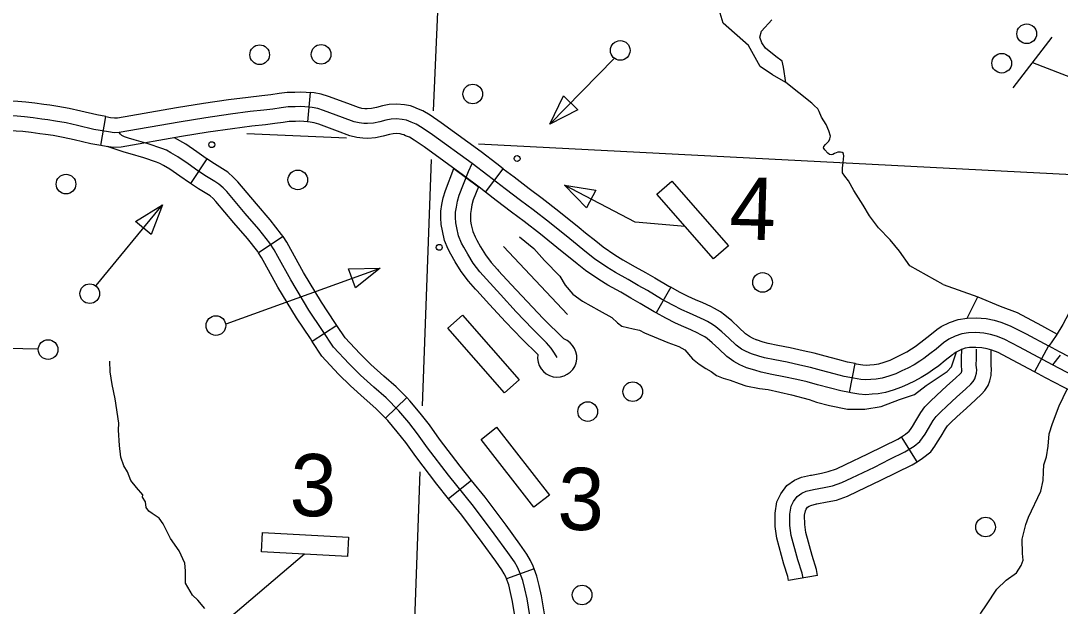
# Model space of a CAD drawing. Extents: x 653372 to 905732, y 627442 to 787275.
# Drawn here: x 714058 to 719343, y 754665 to 757645 of the extents above; entities that cross this region are included whole.
import ezdxf

# ---------------------------------------------------------------- set-up
doc = ezdxf.new("R2010")
doc.units = 0
for name, color, linetype in [('31', 7, 'Continuous'), ('32', 7, 'Continuous'), ('35', 7, 'Continuous'), ('45', 7, 'Continuous'), ('5', 7, 'Continuous'), ('56', 7, 'Continuous')]:
    doc.layers.add(name, color=color, linetype=linetype)

msp = doc.modelspace()

# ---------------------------------------------------------------- linework, layer by layer
at = {"layer": '31'}
for p, q in [((715529.1, 757279.6), (715516.5, 757130.2)), ((714464.6, 757009.8), (714490.5, 757157.5)), ((714490.5, 757157.5), (714490.5, 757157.5)), ((716420, 756772.8), (716511.3, 756891.8)), ((716511.3, 756891.8), (716511.3, 756891.8)), ((717362.4, 756288.6), (717288.8, 756157.9)), ((719283, 755990.6), (719212.1, 755858.4)), ((718271.2, 755753.4), (718299.6, 755900.6)), ((718299.6, 755900.6), (718299.6, 755900.6))]:
    msp.add_line(p, q, dxfattribs=at)
for points in [[(714986.5, 757225.6), (714987.8, 757225.9), (715114.1, 757244.3), (715214.9, 757257), (715284.1, 757264.4), (715329.3, 757270.3), (715372.1, 757276.5), (715411.7, 757281.5), (715451.2, 757282.5), (715479.3, 757283.4), (715508.5, 757281.4), (715529.1, 757279.6)], [(716061.3, 757202.9), (716040.2, 757211.4), (716008.6, 757217.5), (715970.2, 757221.3), (715931.2, 757219), (715896.3, 757211.7), (715866.5, 757203.3), (715840.7, 757198.6), (715818.6, 757196.7), (715808.1, 757197), (715792.2, 757198.8), (715774.6, 757203), (715720.9, 757223.5), (715621.9, 757260.3), (715585.1, 757271.7), (715549.2, 757277.9), (715529.1, 757279.6)], [(714490.5, 757157.5), (714444.3, 757165.6), (714362.8, 757185.2), (714303.2, 757198.7), (714246.7, 757208.7), (714205.4, 757215.3), (714174.6, 757219.2), (714129.8, 757225), (714083.2, 757230.6), (714042.7, 757233.7), (713980.6, 757235.5), (713956.8, 757235.6)], [(714490.5, 757157.5), (714514.5, 757153.3), (714535.1, 757150.7), (714550.1, 757151.6), (714850.2, 757203.3), (714986.5, 757225.6)], [(719135.7, 755984.5), (719058.1, 756024.5), (719018.4, 756039.8), (718989, 756047.7), (718955.5, 756055.1), (718914.7, 756057.7), (718875.9, 756056), (718842, 756051.4), (718808.5, 756039.7), (718776.4, 756023.8), (718749.8, 756005.6), (718711.5, 755974.3), (718680.5, 755949.2), (718649.5, 755926.9), (718628.7, 755912), (718599.7, 755894.7), (718567.5, 755877.3), (718537.5, 755862.7), (718507.5, 755848.8), (718471.2, 755835.8), (718437.1, 755826.3), (718407.4, 755820.9), (718380.5, 755818.8), (718355.1, 755816.8), (718328.5, 755819.7), (718292, 755825.7), (718244.4, 755834.9), (718193.4, 755848.4), (718128.8, 755865.1), (718073.6, 755880.2), (718019.7, 755891.7), (717954, 755907), (717891.7, 755918.7), (717839.9, 755930.2), (717811.3, 755938.1), (717773.6, 755949.8), (717745.8, 755961.2), (717722.9, 755973.8), (717695.5, 755993.6), (717657.8, 756029.3), (717622.9, 756062), (717592.7, 756087.6), (717575.4, 756099.4), (717548.9, 756114.8), (717532.9, 756123), (717496.1, 756140.3), (717458.6, 756156.2), (717419, 756173.6), (717372.5, 756196.8), (717315.7, 756228.8), (717244.5, 756271.8), (717196.7, 756297.9), (717145.5, 756328.3), (717081, 756363.4), (717037.5, 756390.7), (716974.7, 756433.8), (716934.1, 756466), (716849.6, 756534.8), (716746.4, 756617.5), (716663.2, 756682.7), (716598.5, 756731.1), (716520.3, 756790.4), (716433.4, 756857.1), (716353.7, 756917.9), (716151.5, 757064.7), (716098.6, 757100.8), (716067.7, 757119.2), (716043, 757129.4), (716018.9, 757139.1), (715997.6, 757143.3), (715968.8, 757146.1), (715941.2, 757144.5), (715914.1, 757138.8), (715883.4, 757130.2), (715850.7, 757124.2), (715820.7, 757121.6), (715802.7, 757122.1), (715779.3, 757124.8), (715752.5, 757131.1), (715694.4, 757153.4), (715597.7, 757189.2), (715567.5, 757198.6), (715539.6, 757203.5), (715502.8, 757206.6), (715477.9, 757208.3), (715453.4, 757207.6), (715417.4, 757206.7), (715382.3, 757202.2), (715339.6, 757196), (715293, 757189.9), (715223.5, 757182.5), (715124.2, 757170), (714999.3, 757151.8), (714862.6, 757129.4), (714558.8, 757077)], [(716511.3, 756891.8), (716479, 756916.7), (716398.5, 756978.1), (716194.7, 757126), (716139, 757164), (716101.4, 757186.4), (716071.4, 757198.8), (716061.3, 757202.9)], [(714558.8, 757077), (714532.7, 757075.4), (714503.3, 757079.1), (714429, 757092.1), (714345.7, 757112.2), (714288.4, 757125.2), (714234.3, 757134.8), (714194.9, 757141), (714165, 757144.8), (714120.5, 757150.6), (714076, 757155.9), (714038.7, 757158.7), (713979.3, 757160.5), (713829.8, 757161), (713646, 757164.3), (713525.8, 757173.6)], [(715516.5, 757130.2), (715497, 757131.8), (715476.4, 757133.3), (715455.5, 757132.6), (715423, 757131.8), (715392.4, 757127.9), (715349.9, 757121.7), (715301.8, 757115.4), (715232.2, 757108), (715134.3, 757095.7), (715010.8, 757077.6), (715010.7, 757077.6)], [(716005.3, 757063.7), (715997.5, 757066.9), (715986.7, 757069), (715967.3, 757070.9), (715951.2, 757069.9), (715931.9, 757065.9), (715900.3, 757057.1), (715860.8, 757049.8), (715822.8, 757046.5), (715797.3, 757047.3), (715766.4, 757050.8), (715730.4, 757059.3), (715668, 757083.2), (715573.5, 757118.2), (715549.8, 757125.6), (715530.1, 757129), (715516.5, 757130.2)], [(714464.6, 757009.8), (714413.8, 757018.6), (714328.6, 757039.1), (714273.5, 757051.7), (714221.9, 757060.8), (714184.4, 757066.8), (714155.5, 757070.4), (714111.2, 757076.2), (714068.7, 757081.3), (714034.8, 757083.8), (713978.1, 757085.5), (713956.2, 757085.6)], [(715010.7, 757077.6), (714875, 757055.4), (714567.5, 757002.4), (714530.2, 757000.1), (714492.2, 757005), (714464.6, 757009.8)], [(716420, 756772.8), (716387.9, 756797.5), (716308.9, 756857.8), (716108.3, 757003.3), (716058.3, 757037.5), (716034, 757052), (716014.7, 757060), (716005.3, 757063.7)], [(716376.4, 756271.7), (716369.5, 756279.2), (716334, 756320), (716297.1, 756368.2), (716266.4, 756418.1), (716243.9, 756456.4), (716231, 756482.5), (716212.5, 756527.1), (716201.5, 756575.7), (716195.4, 756607.7), (716193.7, 756641.7), (716193.9, 756676.3), (716199.2, 756709.2), (716205.1, 756743.4), (716216.6, 756781.8), (716259.5, 756893.6), (716384.4, 756800.2)], [(716785.1, 755931.3), (716771, 755952.9), (716754.8, 755978), (716731.7, 756006.2), (716660.6, 756077.3), (716577.6, 756164), (716496.4, 756251.7), (716425.5, 756329.2), (716392.1, 756367.5), (716358.9, 756410.8), (716330.7, 756456.7), (716310, 756492.1), (716299.3, 756513.6), (716284.2, 756549.9), (716274.9, 756591.1), (716270.1, 756616.6), (716268.7, 756643.4), (716268.8, 756670.1), (716273.2, 756696.8), (716278.3, 756726.2), (716287.7, 756757.6), (716309.1, 756813.3), (716334.9, 756877.4), (716353.7, 756917.9)], [(716511.3, 756891.8), (716565.8, 756850.1), (716643.6, 756791), (716708.8, 756742.2), (716793, 756676.3), (716896.7, 756593.1), (716929.7, 756566.3)], [(716384.4, 756800.2), (716358.7, 756733.4), (716351.4, 756709), (716347.1, 756684.4), (716343.8, 756664), (716343.8, 756645.1), (716344.7, 756625.5), (716348.3, 756606.4), (716356, 756572.8), (716367.7, 756544.6), (716376, 756527.8), (716395.1, 756495.3), (716420.8, 756453.3), (716450.2, 756415), (716481.5, 756379.1), (716487.1, 756373)], [(716835.1, 756449.9), (716802.5, 756476.4), (716699.9, 756558.7), (716617.6, 756623.1), (716553.3, 756671.2), (716474.8, 756730.8), (716420, 756772.8)], [(716929.7, 756566.3), (716981.1, 756524.5), (717019.3, 756494.2), (717078.7, 756453.4), (717118.9, 756428.1), (717182.5, 756393.5), (717233.8, 756363.1), (717281.8, 756336.9), (717353.5, 756293.6), (717362.4, 756288.6)], [(717288.8, 756157.9), (717277.9, 756164), (717207.1, 756206.8), (717159.5, 756232.7), (717108.4, 756263.1), (717043.1, 756298.6), (716996.3, 756328), (716930.1, 756373.5), (716887.2, 756407.6), (716835.1, 756449.9)], [(716487.1, 756373), (716551.6, 756302.5), (716632.1, 756215.4), (716714.3, 756129.8), (716818.3, 756025.6)], [(716686.2, 755945.7), (716607, 756024.9), (716523, 756112.6), (716441.2, 756200.9), (716376.4, 756271.7)], [(717800.8, 756019.7), (717778.3, 756028.9), (717763.2, 756037.3), (717743.4, 756051.5), (717709.3, 756083.9), (717672.8, 756118.1), (717638.2, 756147.3), (717615.4, 756162.9), (717584.9, 756180.6), (717566.1, 756190.3), (717526.7, 756208.8), (717488.3, 756225.1), (717450.8, 756241.5), (717407.7, 756263.1), (717362.4, 756288.6)], [(717743.9, 755880.9), (717713.3, 755893.4), (717682.7, 755910.4), (717647.6, 755935.7), (717606.4, 755974.7), (717573, 756006), (717547.2, 756027.8), (717535.5, 756035.9), (717512.9, 756048.9), (717499.8, 756055.7), (717465.5, 756071.8), (717428.9, 756087.3), (717387.1, 756105.7), (717337.3, 756130.6), (717288.8, 756157.9)], [(718716.5, 756073.7), (718738.3, 756088.7), (718779.4, 756109), (718824.4, 756124.7), (718869.3, 756130.8), (718915.5, 756132.8), (718965.9, 756129.5), (719006.8, 756120.6), (719041.7, 756111.2), (719088.8, 756093), (719170.6, 756050.9), (719283, 755990.6)], [(718299.6, 755900.6), (718305.2, 755899.6), (718338.6, 755894), (718356.2, 755892.1), (718374.7, 755893.6), (718397.8, 755895.3), (718420.2, 755899.4), (718448.4, 755907.3), (718479, 755918.3), (718505.3, 755930.5), (718533.3, 755944.1), (718562.6, 755959.9), (718587.6, 755974.8), (718605.8, 755987.8), (718634.9, 756008.8), (718664.2, 756032.5), (718704.8, 756065.7), (718716.5, 756073.7)], [(718299.6, 755900.6), (718261.1, 755908.1), (718212.4, 755921), (718148, 755937.6), (718091.3, 755953.1), (718036.1, 755964.9), (717969.5, 755980.4), (717906.7, 755992.2), (717858, 756003), (717832.4, 756010), (717799, 756020.4), (717800.8, 756019.7)], [(719212.1, 755858.4), (719100.8, 755918.1), (719027.3, 755956), (718995.1, 755968.4), (718971.2, 755974.8), (718945, 755980.6), (718913.9, 755982.6), (718882.6, 755981.3), (718859.6, 755978.1), (718837.7, 755970.5), (718814.4, 755958.9), (718801.3, 755949.9)], [(719442.4, 755821.2), (719303.9, 755894.3), (719135.7, 755984.5)], [(719702.6, 755600.9), (719700.3, 755623.4), (719690.5, 755664.1), (719675, 755704.8), (719651.2, 755742.5), (719630.3, 755770.3), (719602.2, 755799.4), (719576.4, 755824), (719538.4, 755850.5), (719479.5, 755886.4), (719339.1, 755960.5), (719283, 755990.6)], [(718801.2, 755949.9), (718794.8, 755945.5), (718758.8, 755916.1), (718726, 755889.6), (718693.2, 755865.9), (718669.8, 755849.2), (718636.8, 755829.4), (718601.7, 755810.6), (718569.6, 755795), (718535.9, 755779.4), (718494, 755764.3), (718454, 755753.1), (718416.9, 755746.4), (718386.4, 755744.1), (718354.1, 755741.5), (718318.3, 755745.4), (718278.8, 755751.9), (718271.2, 755753.4)], [(718271.2, 755753.4), (718227.7, 755761.7), (718174.4, 755775.9), (718109.5, 755792.7), (718055.9, 755807.3), (718003.4, 755818.5), (717938.5, 755833.6), (717876.7, 755845.3), (717821.9, 755857.3), (717790.2, 755866.1), (717748.2, 755879.1), (717743.9, 755880.9)], [(719553.4, 755585.3), (719552.1, 755598), (719546.9, 755619.8), (719540.2, 755637.5), (719527.7, 755657.2), (719516.1, 755672.7), (719496.4, 755692.9), (719481.1, 755707.6), (719456.4, 755724.8), (719405.3, 755756), (719268.7, 755828.1), (719212.1, 755858.4)]]:
    msp.add_lwpolyline(points, dxfattribs=at)
msp.add_arc((716785.1, 755931.3), 100, 171.739, 70.6256, dxfattribs=at)
at = {"layer": '32'}
for p, q in [((715003.8, 756941.7), (714921.6, 756816.2)), ((715391.5, 756546.6), (715266.4, 756463.8)), ((715665.2, 756094.8), (715539.5, 756013)), ((716020, 755727), (715913.1, 755621.8)), ((716350.1, 755305.5), (716233, 755211.8)), ((716668.2, 754856.1), (716527.5, 754804.1))]:
    msp.add_line(p, q, dxfattribs=at)
for points in [[(716652.6, 754575.1), (716632.2, 754703.5), (716621.5, 754753), (716610.6, 754795.7), (716594.4, 754839.5), (716583, 754864.2), (716568.2, 754890.4), (716535.1, 754938.2), (716464.9, 755033.7), (716359.2, 755174.2), (716232.5, 755332.3), (716126.7, 755471.8), (716075.4, 755543.4), (716030.3, 755600.3), (715980.6, 755660.2), (715915.4, 755726.4), (715853.7, 755779.9), (715785.5, 755841.3), (715727.9, 755899), (715647.7, 755984.2), (715592.8, 756068.6), (715522.9, 756172.9), (715430.2, 756326.6), (715364.7, 756445.4), (715345.8, 756479.8), (715323.4, 756513.6), (715268.6, 756584.4), (715199, 756664.8), (715105, 756775.7), (715087.6, 756794.2), (715065.3, 756813.9), (715043.8, 756827.2), (715002.2, 756853), (714957.8, 756882.1), (714909.2, 756916.2), (714856.3, 756953.3), (714820.9, 756973.4), (714798.4, 756985.7), (714775.8, 756995.7), (714705.2, 757019.2), (714634.7, 757039.3), (714606.3, 757047.5), (714585.1, 757054.4), (714571.2, 757061.7), (714564.1, 757068.7), (714558.8, 757077)], [(715003.8, 756941.7), (714999.9, 756944.2), (714952.3, 756977.6), (714896.4, 757016.8), (714839.1, 757049.2)], [(714921.6, 756816.2), (714915.7, 756820), (714866.1, 756854.8), (714816.2, 756889.8), (714784.4, 756907.9), (714765.2, 756918.4), (714748.8, 756925.6), (714683, 756947.5), (714614.1, 756967.2), (714584.2, 756975.8), (714497.5, 757004.3)], [(715391.5, 756546.6), (715384.4, 756557.3), (715326.7, 756631.9), (715256, 756713.6), (715161, 756825.7), (715139.8, 756848.2), (715110.1, 756874.3), (715083.3, 756890.9), (715042.6, 756916.3), (715003.8, 756941.7)], [(715266.4, 756463.8), (715262.4, 756469.9), (715210.6, 756536.8), (715142, 756616), (715049.1, 756725.7), (715035.3, 756740.3), (715020.4, 756753.5), (715004.3, 756763.5), (714961.9, 756789.8), (714921.6, 756816.2)], [(715665.2, 756094.8), (715655.4, 756109.9), (715586.2, 756213.2), (715495.2, 756364.1), (715430.4, 756481.6), (715410, 756518.6), (715391.5, 756546.6)], [(715539.5, 756013), (715530.2, 756027.3), (715459.6, 756132.6), (715365.3, 756289.1), (715299, 756409.2), (715281.5, 756441), (715266.4, 756463.8)], [(719563.3, 756393.3), (719511.2, 756333.2), (719478.2, 756295.1), (719452.7, 756258.8), (719426.6, 756224.2), (719400.6, 756182.9), (719356, 756100), (719322.8, 756043), (719284.6, 755989.7)], [(716020, 755727), (715966.8, 755781.1), (715903.4, 755836.1), (715837.2, 755895.7), (715781.7, 755951.2), (715706.9, 756030.7), (715665.2, 756094.8)], [(715913.1, 755621.8), (715864, 755671.7), (715804.1, 755723.6), (715733.8, 755786.9), (715674, 755846.8), (715588.5, 755937.7), (715539.5, 756013)], [(719343.6, 755943.3), (719303.9, 755894.3)], [(716350.1, 755305.5), (716291.7, 755378.4), (716187.1, 755516.3), (716135.3, 755588.6), (716088.6, 755647.5), (716036.2, 755710.5), (716020, 755727)], [(716233, 755211.8), (716173.4, 755286.2), (716066.4, 755427.3), (716015.5, 755498.3), (715972.1, 755553), (715924.9, 755609.8), (715913.1, 755621.8)], [(716668.2, 754856.1), (716663.7, 754868.3), (716649.8, 754898.4), (716631.8, 754930.3), (716596.1, 754981.7), (716525.1, 755078.5), (716418.4, 755220.2), (716350.1, 755305.5)], [(716527.5, 754804.1), (716525.1, 754810.7), (716516.2, 754830), (716504.6, 754850.6), (716474, 754894.6), (716404.7, 754989), (716299.9, 755128.2), (716233, 755211.8)], [(716768, 754322.8), (716764.7, 754345.1), (716740.4, 754489.8), (716726.8, 754586.3), (716705.9, 754717.3), (716694.5, 754770.2), (716682.3, 754818), (716668.2, 754856.1)], [(716619.7, 754300.7), (716616.6, 754321.6), (716592.2, 754466.9), (716578.5, 754564), (716558.4, 754689.7), (716548.5, 754735.8), (716538.9, 754773.3), (716527.5, 754804.1)]]:
    msp.add_lwpolyline(points, dxfattribs=at)
at = {"layer": '35'}
for points in [[(718079.8, 757226.2), (717947.3, 757330.7), (717879.3, 757370.3), (717816.8, 757413), (717757.3, 757518.5), (717628.9, 757632.3), (717614.8, 757683.6)], [(717947.3, 757330.7), (717936, 757409.3), (717929.1, 757438.9), (717896.5, 757463.3), (717845, 757506), (717826.2, 757532), (717815.4, 757561.7), (717824.1, 757592.7), (717876.7, 757649.9)], [(718747.9, 756303.1), (718578.9, 756397), (718525.9, 756472.4), (718479, 756530.9), (718418.8, 756591.4), (718373.6, 756651.5), (718341.7, 756706.1), (718293.7, 756781.4), (718266.6, 756829.7), (718247.2, 756853.8), (718236.8, 756871.7), (718235.9, 756895.2), (718239.2, 756923.6), (718243.6, 756956.9), (718240.5, 756965.5), (718240.6, 756969.7), (718234.9, 756974.9), (718225.7, 756976.9), (718213.1, 756975.6), (718195.3, 756969.4), (718187.6, 756963.8), (718179.2, 756963.2), (718169.2, 756965.2), (718161.8, 756970.4), (718146.4, 756987.7), (718140, 756997.9), (718141.9, 757005.4), (718148.9, 757015.3), (718166.2, 757031.5), (718172.4, 757043.9), (718174.5, 757058.1), (718166.9, 757085.2), (718153.6, 757116.6), (718128.8, 757155.1), (718117.9, 757183.1), (718109.9, 757196.8), (718091.2, 757214.1), (718079.8, 757226.2)], [(716593.4, 756545.2), (716666.2, 756485.2), (716721.2, 756424.3), (716798.5, 756345.9), (716826, 756300), (716865.5, 756254.4), (716913.6, 756217.1), (716998.8, 756170.8), (717063.3, 756135.1), (717092.7, 756107.4), (717114.8, 756091.3), (717143.4, 756083.4), (717172.1, 756077.6), (717204.3, 756070.3), (717228.5, 756056.9), (717347.6, 756007.2), (717404, 755986.4), (717434.5, 755970), (717473.3, 755925.2), (717507.7, 755896.7), (717540.9, 755876), (717568.5, 755859.6), (717595.4, 755839.8), (717629.5, 755826.8), (717665.1, 755816.6), (717710.4, 755799.7), (717745.2, 755787.4), (717813.8, 755773.4), (717858, 755768.5), (717976.9, 755741.3), (718066, 755716.9)], [(718747.9, 756303.1), (718923.4, 756239.3), (719037, 756193), (719124.8, 756159.8), (719248.4, 756094.7), (719327.6, 756049.7)], [(718869.3, 756130.8), (718923.4, 756239.3)], [(718066, 755716.9), (718104.4, 755704.3), (718170.7, 755687), (718261.7, 755668.8), (718350.4, 755667.5), (718432.5, 755681.9), (718525.1, 755717.2), (718602.8, 755742.3), (718661.1, 755788.3), (718768.3, 755860.1), (718791.1, 755883.9), (718815.2, 755959.5)], [(714993.9, 754653.1), (714958.4, 754695.7), (714931.5, 754721.3), (714895.8, 754782.1), (714896.2, 754844.9), (714892.8, 754883.9), (714862.6, 754947.5), (714818.4, 755009.6), (714782.4, 755084.4), (714761, 755113.4), (714725.8, 755137.9), (714708.9, 755148.8), (714694.7, 755168.1), (714691.4, 755196), (714677.1, 755220.9), (714678.3, 755232.7), (714647.1, 755269.8), (714617.3, 755305.6), (714599.9, 755348.6), (714582.7, 755380.4), (714566.7, 755423.4), (714560.2, 755483.3), (714554.8, 755561.3), (714555.7, 755596.2), (714537, 755721.5), (714523.4, 755793.8), (714512.6, 755857.6), (714510.4, 755912)], [(718820.4, 754381.6), (718867.8, 754501.1), (718914.3, 754586.1), (718938.9, 754629.3), (718969, 754672.2), (719020.7, 754751.6), (719067.4, 754798.2), (719120.6, 754835.1), (719143.7, 754872.8), (719154.1, 754899.9), (719151, 754932.9), (719149.1, 755007), (719167.8, 755081.9), (719181.2, 755118.6), (719244.2, 755250.4), (719256.8, 755304.9), (719258.1, 755350.1), (719259.2, 755385.7), (719274.1, 755425.1), (719282.6, 755479.4), (719287.2, 755542.4), (719304.6, 755594.6), (719338.5, 755685.3), (719379.1, 755769.8)]]:
    msp.add_lwpolyline(points, dxfattribs=at)
at = {"layer": '45'}
for p, q in [((718615.3, 755401), (718535.2, 755527.9)), ((718109.6, 754821.4), (717961.7, 754796.4))]:
    msp.add_line(p, q, dxfattribs=at)
for points in [[(718035.7, 754808.9), (718031.4, 754834), (718009.5, 754901.6), (717975.2, 755025.5), (717968.8, 755076.7), (717968.5, 755133.7), (717974.7, 755174.5), (717986.4, 755198.1), (718006.2, 755224.5), (718029.6, 755240.8), (718050.9, 755250.1), (718089.1, 755259), (718143.4, 755269.3), (718184.6, 755278.1), (718233.1, 755295.6), (718282.7, 755318.1), (718398.3, 755373.6), (718477.4, 755413), (718553.5, 755450.7), (718600.3, 755480.3), (718630, 755503.4), (718643.5, 755521.9), (718655.8, 755541.2), (718672.6, 755569.7), (718696.8, 755609.9), (718712.4, 755631.4), (718734.1, 755653.8), (718767, 755683.8), (718815.3, 755729.3), (718862.5, 755771.8), (718889.2, 755796), (718899.6, 755808.3), (718908.5, 755822.1), (718912.8, 755833.9), (718916.8, 755851.3), (718918.3, 755867.7), (718916.1, 755891.8), (718916.6, 755925.7), (718917.1, 755974.1)], [(718842.5, 755861.9), (718843, 755867.6), (718841, 755888.8), (718841.6, 755926.7), (718842.1, 755975.7)], [(718991.9, 755848.3), (718993.7, 755867.9), (718991.1, 755894.7), (718991.6, 755924.8), (718992.1, 755969.6)], [(718535.2, 755527.9), (718557.1, 755541.7), (718575.6, 755556.1), (718581.5, 755564.2), (718591.9, 755580.5), (718608.2, 755608.1), (718634.2, 755651.4), (718654.9, 755679.8), (718681.8, 755707.6), (718716, 755738.8), (718764.5, 755784.5), (718812.2, 755827.5), (718835.1, 755848.2), (718839.2, 755853.1), (718840.9, 755855.7), (718842.6, 755863.2), (718842.5, 755861.9)], [(718615.3, 755401), (718643.5, 755418.8), (718684.4, 755450.7), (718705.5, 755479.7), (718719.7, 755501.9), (718737, 755531.3), (718759.4, 755568.5), (718770, 755583.1), (718786.3, 755599.9), (718817.9, 755628.8), (718866.1, 755674.1), (718912.8, 755716.2), (718943.3, 755743.8), (718959.9, 755763.6), (718976, 755788.3), (718984.8, 755812.5), (718991.1, 755839.4), (718991.9, 755848.3)], [(718077.7, 755333.1), (718128.6, 755342.9), (718164, 755350.4), (718204.8, 755365.2), (718251, 755386.1), (718365.3, 755441), (718444, 755480.2), (718516.7, 755516.2), (718535.2, 755527.9)], [(718105.8, 755185.8), (718158.2, 755195.8), (718205.3, 755205.8), (718261.4, 755226.1), (718314.4, 755250.2), (718431.2, 755306.2), (718510.8, 755345.8), (718590.2, 755385.2), (718615.3, 755401)], [(717961.7, 754796.4), (717958.4, 754816.1), (717937.6, 754880), (717901.5, 755010.8), (717893.8, 755071.8), (717893.5, 755139.2), (717902.3, 755197.3), (717922.2, 755237.6), (717953.4, 755279.2), (717992.8, 755306.5), (718027.1, 755321.6), (718073.6, 755332.4), (718077.7, 755333.1)], [(718109.6, 754821.4), (718104.4, 754851.9), (718081.3, 754923.2), (718049, 755040.3), (718043.7, 755081.6), (718043.5, 755128.2), (718047.1, 755151.6), (718050.6, 755158.6), (718058.9, 755169.8), (718066.5, 755175), (718074.7, 755178.6), (718104.6, 755185.6), (718105.8, 755185.8)]]:
    msp.add_lwpolyline(points, dxfattribs=at)
at = {"layer": '5'}
for points in [[(716320, 760986.6), (716154.7, 757186)], [(715206.8, 757072), (715714.3, 757049.5)], [(716385, 757018.2), (719863, 756839.5)], [(716144.7, 756938.3), (716099.4, 755684.9)], [(716087.3, 755349.9), (715957.5, 751756.8)]]:
    msp.add_lwpolyline(points, dxfattribs=at)
at = {"layer": '56'}
for p, q in [((716747.4, 757118.1), (716817.8, 757263.2)), ((716817.8, 757263.2), (716890.8, 757191.9)), ((716890.8, 757191.9), (716747.4, 757118.1)), ((716934.5, 756692.3), (716822.8, 756808.6)), ((716822.8, 756808.6), (716981.9, 756782.6)), ((716981.9, 756782.6), (716934.5, 756692.3)), ((714641.3, 756622.7), (714777.7, 756708.7)), ((714777.7, 756708.7), (714720.2, 756558)), ((714720.2, 756558), (714641.3, 756622.7)), ((715724.6, 756381.8), (715885.9, 756385.9)), ((715759.3, 756285.9), (715724.6, 756381.8)), ((715885.9, 756385.9), (715759.3, 756285.9))]:
    msp.add_line(p, q, dxfattribs=at)
for points in [[(719103, 757303.6), (719301.3, 757560.9)], [(717074.4, 757452.8), (716747.4, 757118.1)], [(719202.2, 757432.2), (719843.1, 757185.7)], [(717436.8, 756598.6), (717181.1, 756620.4), (716822.8, 756808.6)], [(714440.6, 756297.4), (714777.7, 756708.7)], [(716512.3, 756496.8), (716838.2, 756150.7)], [(715101.6, 756102.1), (715885.9, 756385.9)], [(714144.6, 755973.2), (713681.5, 755984.4)], [(715500.5, 754929.5), (714828.7, 754357.7)]]:
    msp.add_lwpolyline(points, dxfattribs=at)
for points in [[(717292.8, 756763.2), (717368, 756829.1), (717656.1, 756499.8), (717580.8, 756433.9)], [(716229.2, 756080.7), (716304.5, 756146.6), (716592.5, 755817.3), (716517.3, 755751.4)], [(716398.2, 755514.5), (716477.3, 755575.8), (716745.4, 755230.1), (716666.4, 755168.8)], [(715282.1, 754941.4), (715287.5, 755041.2), (715724.4, 755017.5), (715718.9, 754917.6)]]:
    msp.add_lwpolyline(points, close=True, dxfattribs=at)
for centre, radius in [((719172.7, 757578.9), 50), ((715272.5, 757472.3), 50), ((715584.9, 757474.1), 50), ((717106, 757494.3), 50), ((719045.6, 757429.2), 50), ((716356, 757272.3), 50), ((715028.8, 757014.4), 15), ((716581.7, 756943.7), 15), ((715466.6, 756835.1), 50), ((714287.9, 756813.7), 50), ((716185.8, 756491.9), 15), ((717829.4, 756313.4), 50), ((714408.9, 756256.2), 50), ((715050.1, 756093.7), 50), ((714196.8, 755971.6), 50), ((717169.7, 755757.3), 50), ((716940.5, 755655.9), 50), ((718963.4, 755068.3), 50), ((716911.9, 754722.5), 50)]:
    msp.add_circle(centre, radius, dxfattribs=at)

# ---------------------------------------------------------------- texts
for s, p in [('4', (717658, 756534.7)), ('3', (715422.4, 755126.7)), ('3', (716784.1, 755056.6))]:
    msp.add_text(s, height=316.8, rotation=358.28, dxfattribs=at).set_placement(p)

doc.saveas('drawing.dxf')
